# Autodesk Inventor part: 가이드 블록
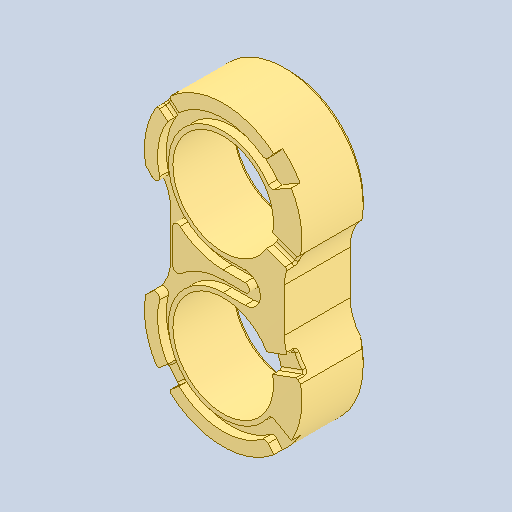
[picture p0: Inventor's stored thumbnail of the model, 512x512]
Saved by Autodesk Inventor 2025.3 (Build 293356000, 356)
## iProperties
Created: 2025-10
Part Number: 가이드 블록
Material: 강철, 주조
Document SubType Name: Modeling
Designer: PC-15
Density: 7.85 g/cm^3
Appearance: 기본값
Author: jhkim
Sending System: Autodesk Inventor 2026
Preprocessor: ST-DEVELOPER v20.1
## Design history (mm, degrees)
feature "솔리드1"
node "솔리드2"
